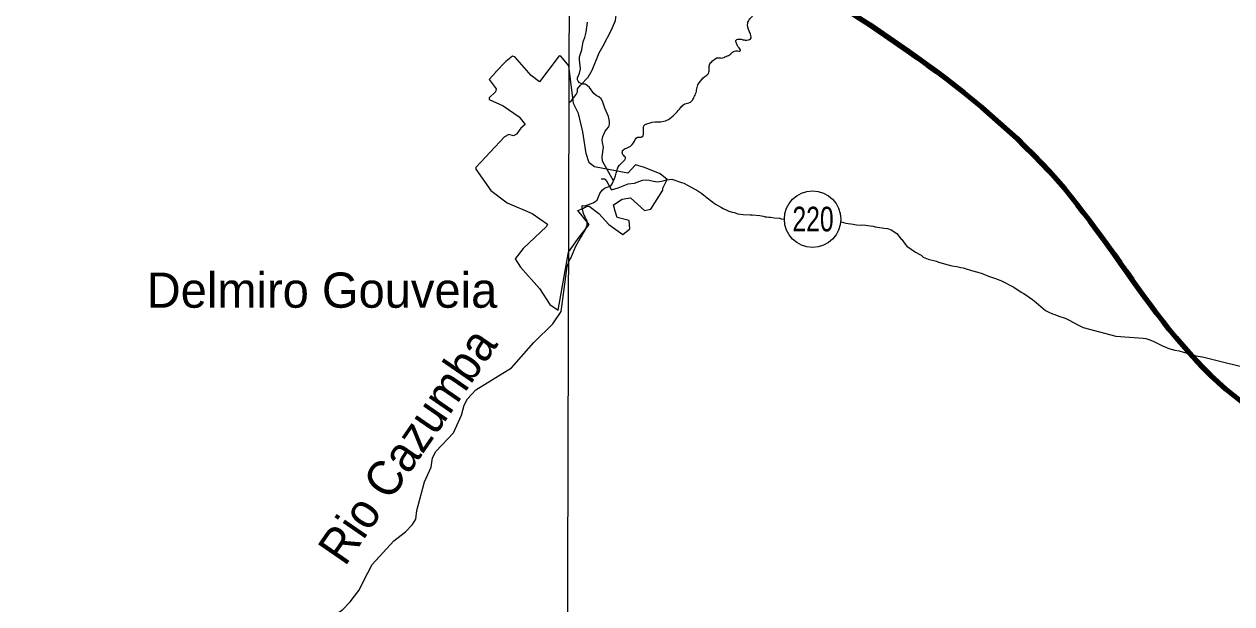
# Model space of a CAD drawing. Extents: x 553962 to 842807, y 8883888 to 9032388.
# Drawn here: x 602069 to 619221, y 8956199 to 8964433 of the extents above; entities that cross this region are included whole.
import ezdxf
from ezdxf.enums import TextEntityAlignment as Align

# ---------------------------------------------------------------- set-up
doc = ezdxf.new("R2010")
doc.units = 0
doc.header["$LTSCALE"] = 20
doc.header["$PDMODE"] = 32
doc.header["$PDSIZE"] = 10
for name, color, linetype, lineweight in [('1', 7, 'Continuous', 13), ('12', 7, 'Continuous', 25), ('21', 7, 'Continuous', 25), ('24', 7, 'Continuous', 25), ('48', 7, 'Continuous', 25), ('9', 7, 'Continuous', 90)]:
    doc.layers.add(name, color=color, linetype=linetype, lineweight=lineweight)
doc.layers.add('41', color=7, linetype='Continuous')
doc.layers.add('49', color=7, linetype='Continuous')

msp = doc.modelspace()

# ---------------------------------------------------------------- linework, layer by layer
at = {"layer": '1'}
msp.add_lwpolyline([(609971.86, 9023551.79), (609764.7, 8949706.73), (609734.23, 8939404.42)], dxfattribs=at)
at = {"layer": '12'}
for points in [[(609806.76, 8963316.15), (609840.08, 8963350.49), (609910.52, 8963433.73), (609927.64, 8963470.82), (609929.64, 8963512.89), (609970.71, 8963564.03), (610080.08, 8963678.38), (610134.08, 8963777.62), (610234.64, 8964027.17), (610293.39, 8964122.41), (610411.71, 8964350.96), (610469.14, 8964484.26), (610483.52, 8964599.46), (610535.46, 8964754.78), (610616.83, 8964899.14), (610667.39, 8964945.29), (610786.39, 8965043.63), (610825.33, 8965173.9), (610880.77, 8965525.53), (610933.39, 8965820.08), (610973.02, 8965953.35)], [(610264.14, 8962237.43), (610311.08, 8962234.5), (610316.02, 8962231.5), (610349.39, 8962192.49), (610374.64, 8962139.45), (610404.71, 8962083.41), (610408.21, 8962079.41), (610506.08, 8962105.6), (610649.08, 8962166.93), (610736.52, 8962174.07), (610812.14, 8962204.24), (610848.71, 8962215.32), (610911.77, 8962219.42), (610943.71, 8962217.47), (611006.14, 8962203.55), (611065.83, 8962194.63), (611093.77, 8962196.68), (611122.52, 8962202.73), (611157.71, 8962212.8), (611189.77, 8962219.86), (611269.64, 8962231.01), (611402.58, 8962182.14), (611435.46, 8962173.18), (611490.08, 8962144.22), (611638.52, 8962063.33), (611691.14, 8962029.36), (611771.08, 8961966.39), (611829.33, 8961918.4), (611889.14, 8961876.43), (611971.14, 8961828.49), (611997.83, 8961813.51), (612050.64, 8961788.55), (612077.02, 8961777.58), (612125.58, 8961761.63), (612153.71, 8961756.67), (612204.89, 8961738.72), (612281.64, 8961727.82), (612380.08, 8961722.97), (612410.52, 8961723.02), (612515.14, 8961715.17), (612566.33, 8961705.24), (612591.89, 8961698.27), (612616.64, 8961694.3), (612643.02, 8961692.34), (612669.46, 8961691.38), (612719.77, 8961683.45), (612795.64, 8961675.55), (612823.83, 8961668.59), (612864.62, 8961663.75)], [(613672.09, 8961625.44), (613738.39, 8961606.94), (613840.64, 8961591.08), (613866.27, 8961585.11), (613888.89, 8961581.14), (613942.14, 8961579.22), (613971.71, 8961581.27), (614023.08, 8961578.34), (614049.52, 8961572.38), (614124.46, 8961561.48), (614153.58, 8961554.51), (614252.33, 8961537.64), (614280.52, 8961536.69), (614332.52, 8961530.76), (614381.96, 8961510.81), (614463.33, 8961460.86), (614523.77, 8961379.83), (614532.21, 8961372.83), (614580.21, 8961308.81), (614605.89, 8961280.8), (614728.58, 8961192.86), (614806.46, 8961149.91), (614838.89, 8961123.93), (614908.02, 8961094.99), (615024.64, 8961065.13), (615056.58, 8961054.16), (615245.08, 8961000.38), (615313.21, 8960990.47), (615372.02, 8960976.54), (615403.58, 8960970.58), (615432.52, 8960962.61), (615522.96, 8960932.71), (615612.39, 8960910.82), (615673.02, 8960889.88), (615762.58, 8960852.96), (615820.39, 8960833.02), (615879.21, 8960814.09), (615909.96, 8960801.12), (615940.89, 8960791.15), (616125.27, 8960698.3), (616228.08, 8960625.35), (616267.39, 8960608.38), (616387.89, 8960522.44), (616444.08, 8960477.46), (616541.08, 8960393.48), (616574.96, 8960367.49), (616612.02, 8960346.52), (616675.83, 8960318.57), (616704.77, 8960308.6), (616763.64, 8960286.66), (616854.77, 8960258.76), (616911.89, 8960228.81), (616972.52, 8960193.85), (617032.96, 8960160.89), (617107.94, 8960123.07)], [(617107.94, 8960123.07), (617571.33, 8960000.09), (617961.21, 8959971.07), (617997.02, 8959967.12), (618026.02, 8959959.15), (618054.02, 8959949.18), (618114.71, 8959924.23), (618235.71, 8959862.33), (618293.71, 8959838.38), (618327.46, 8959827.42), (618413.02, 8959804.52), (618473.52, 8959791.6), (618533.21, 8959772.66), (618617.89, 8959748.76), (618652.52, 8959740.8), (618682.39, 8959731.83), (618711.39, 8959723.87), (618803.58, 8959708.99), (619586.31, 8959511.32)]]:
    msp.add_lwpolyline(points, dxfattribs=at)
at = {"layer": '21'}
for points in [[(609804.26, 8963841.64), (609692.78, 8963976.15), (609666.56, 8963982.65), (609387.81, 8963613.48), (609268.73, 8963704.28), (609037.74, 8963969.69), (609005.22, 8963976.31), (608907.93, 8963902.9), (608765.24, 8963749.44), (608768.43, 8963752.88)], [(609800.83, 8961196.1), (609951.32, 8961405.54), (610091.23, 8961585.48), (609931.33, 8961785.42), (610001.29, 8961815.41), (610061.25, 8961845.4), (610091.23, 8961845.4), (610231.14, 8961745.43), (610371.05, 8961585.48), (610570.92, 8961445.53), (610670.85, 8961525.5), (610660.86, 8961645.47), (610490.97, 8961685.45), (610460.99, 8961775.42), (610441, 8961865.39), (610560.92, 8961945.37), (610680.84, 8961965.36), (610880.71, 8961785.42), (610970.65, 8961805.41), (611140.54, 8962075.32), (611140.54, 8962105.31), (611200.51, 8962225.28), (611100.57, 8962305.25), (610880.71, 8962395.22), (610750.8, 8962435.21), (610640.87, 8962315.25), (610391.03, 8962365.23), (610171.18, 8962405.22), (610091.23, 8962465.2), (610051.25, 8962595.15), (610001.29, 8962905.05), (609941.33, 8963164.97), (609871.37, 8963304.92), (609804.26, 8963841.64)], [(608768.43, 8963752.88), (608671.82, 8963644.45), (608771.6, 8963513.53), (608762.99, 8963472.77), (608674.68, 8963384.28), (608674.59, 8963362.56), (608871.14, 8963271.64), (609098.61, 8963116.94), (609185.23, 8963006.15), (609122.63, 8962955.37), (609059.51, 8962870.65), (609020.31, 8962848.1), (608953.33, 8962867.29), (608890.22, 8962830.94), (608482.27, 8962396.29), (608482.15, 8962374.58), (608698.72, 8962069.66), (608927.38, 8961894.67), (609281.9, 8961745.45), (609499.96, 8961592.09), (609485.03, 8961557.46), (609154.37, 8961246.08), (609040.78, 8961101.43), (609118.97, 8960979.48), (609387.81, 8960677.54), (609534.3, 8960449.09), (609653.75, 8960372.8), (609800.83, 8961196.1)]]:
    msp.add_lwpolyline(points, dxfattribs=at)
at = {"layer": '24'}
for points in [[(610371.41, 8962976.19), (610379.77, 8963013.82), (610382.08, 8963047.88), (610367.52, 8963119.97), (610314.83, 8963239.07), (610282.27, 8963338.17), (610265.39, 8963370.2), (610232.83, 8963402.19), (610193.27, 8963421.16), (610157.77, 8963448.15), (610095.58, 8963532.18), (610066.71, 8963561.18), (610036.58, 8963580.16), (610003.64, 8963581.11), (609956.21, 8963599.06), (609935.96, 8963623.07), (609928.64, 8963640.08), (609929.46, 8963669.13), (609954.39, 8963735.27), (609968.27, 8963800.4), (609967.71, 8963842.46), (609955.27, 8963923.57), (609957.64, 8963969.65), (609987.33, 8964065.84), (610009.71, 8964184.06), (610029.89, 8964242.18), (610049.39, 8964318.33), (610070.58, 8964459.59)], [(609982.08, 8961422.71), (610037.08, 8961507.93), (610064.52, 8961578.08), (610064.21, 8961638.18), (610040.64, 8961677.2), (610038.14, 8961690.22), (610013.27, 8961743.26), (609992.64, 8961823.35), (609993.52, 8961853.4), (609997.64, 8961856.41), (610025.71, 8961851.45), (610048.08, 8961855.49), (610148.52, 8961896.71), (610207.64, 8961933.86), (610245.08, 8962026.07), (610277.64, 8962073.19), (610312.83, 8962103.29), (610398.58, 8962138.48), (610419.46, 8962164.56), (610435.71, 8962195.63), (610437.21, 8962206.65), (610284.46, 8962485.85), (610279.77, 8962547.94), (610295.52, 8962684.17), (610281.33, 8962752.26), (610279.83, 8962791.32), (610289.02, 8962838.4), (610320.02, 8962910.56), (610338.83, 8962938.64), (610371.41, 8962976.19)], [(606950.74, 8956641.4), (607010.66, 8956757.79), (607320.69, 8957095.59), (607486.36, 8957220.94), (607586.35, 8957325.27), (607630.85, 8957401.73), (607645.73, 8957526.82), (607756.69, 8957933.83), (607847.37, 8958140.8), (607868.86, 8958272.66), (607915.5, 8958363.76), (608166.08, 8958629.35), (608279.75, 8958879.28), (608316.99, 8959022.29), (608365.84, 8959111.5), (608484.8, 8959236.81), (608990.15, 8959553.21), (609306.87, 8959910.22), (609576.63, 8960175.78), (609697.73, 8960349.96), (609780.49, 8960991.96), (609809.77, 8961070.89), (609834.02, 8961109.99), (609904.77, 8961278.36), (609982.08, 8961422.71)], [(606039.31, 8955103.84), (605929.59, 8955224.49), (605999.41, 8955353.7), (606179.95, 8955619.26), (606269.21, 8955840.15), (606360.18, 8955926.93), (606411.54, 8955999.45), (606589.93, 8956112.09), (606699.78, 8956226.08), (606821.62, 8956390.61), (606950.74, 8956641.4)]]:
    msp.add_lwpolyline(points, dxfattribs=at)
msp.add_spline([(610437.21, 8962206.65), (610489.25, 8962352.46), (610506.96, 8962405.63), (610591.1, 8962494.25), (610608.81, 8962534.13), (610568.96, 8962587.3), (610568.96, 8962636.04), (610622.09, 8962671.49), (610723.94, 8962746.82), (610781.51, 8962826.57), (610843.5, 8962831), (610865.64, 8962932.92), (610878.93, 8962999.38), (610927.63, 8963021.53), (610989.63, 8963039.26), (611153.47, 8963052.55), (611237.6, 8963092.43), (611326.19, 8963170.26), (611391.11, 8963243.77), (611437.23, 8963291.63), (611507.27, 8963317.27), (611551.69, 8963341.2), (611579.02, 8963390.78), (611611.48, 8963460.86), (611625.15, 8963534.37), (611655.9, 8963601.04), (611737.9, 8963688.22), (611785.74, 8963732.66), (611797.69, 8963804.46), (611807.95, 8963871.13), (611830.16, 8963895.06), (611896.78, 8963948.06), (611918.99, 8963954.89), (611970.24, 8963951.47), (612038.57, 8963975.41), (612098.37, 8964004.47), (612127.41, 8964033.53), (612190.62, 8964055.75), (612224.79, 8964050.62), (612238.45, 8964052.33), (612240.16, 8964069.42), (612205.99, 8964115.58), (612185.49, 8964161.73), (612176.95, 8964187.38), (612183.78, 8964207.89), (612226.49, 8964221.56), (612276.04, 8964211.31), (612310.2, 8964206.18), (612354.62, 8964207.89), (612385.37, 8964224.98), (612393.91, 8964254.04), (612385.37, 8964289.94), (612343.52, 8964423.29), (612364.02, 8964491.67), (612418.68, 8964560.05), (612432.35, 8964642.1), (612411.85, 8964730.99), (612405.02, 8964792.53), (612418.68, 8964867.75), (612514.35, 8965059.21), (612562.19, 8965113.91), (612657.85, 8965195.96), (612753.52, 8965380.58), (612828.69, 8965387.42), (612876.52, 8965339.56), (612965.36, 8965373.74), (612931.19, 8965585.72), (612903.86, 8965667.77), (612944.86, 8965818.2), (612917.52, 8966009.66), (612951.69, 8966173.76), (612931.2, 8966378.91), (612992.7, 8966488.31), (612992.7, 8966625.07), (613020.03, 8966679.77), (612979.03, 8966789.17), (613026.86, 8966830.2), (613095.2, 8966850.71), (613136.2, 8967014.82), (613067.86, 8967213.11), (612965.36, 8967260.98), (612938.03, 8967343.03), (612883.36, 8967397.73), (612787.69, 8967425.09), (612753.53, 8967452.44), (612705.69, 8967520.81), (612658.63, 8967543.88), (612640.14, 8967590.13), (612640.14, 8967642.55), (612667.87, 8967707.31), (612667.87, 8967747.39)], degree=3, dxfattribs=at)
msp.add_point((609982.08, 8961422.71), dxfattribs=at)
at = {"layer": '48'}
msp.add_circle((613266.4, 8961662.93), 401.28, dxfattribs=at)
at = {"layer": '9'}
msp.add_spline([(592698.54, 8977198.44), (599903.54, 8973292.71), (608459.22, 8968138.19), (612674.79, 8965332.64), (616842.02, 8962096.37), (620004.97, 8958671.19), (621133.98, 8957974.71), (621473.43, 8956805.35), (621586.23, 8956597.47)], degree=3, dxfattribs=at)

# ---------------------------------------------------------------- texts
at = {"layer": '41'}
msp.add_text('Delmiro Gouveia', height=500, dxfattribs=at).set_placement((603808.91, 8960405.19))
at = {"layer": '48', "width": 0.75}
msp.add_text('220', height=350, dxfattribs=at).set_placement((613273.05, 8961489.58), align=Align.CENTER)
at = {"layer": '49', "width": 0.95}
msp.add_text('Rio Cazumba', height=500, rotation=55.429, dxfattribs=at).set_placement((607716.77, 8958303), align=Align.CENTER)

doc.saveas('drawing.dxf')
